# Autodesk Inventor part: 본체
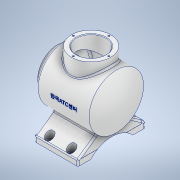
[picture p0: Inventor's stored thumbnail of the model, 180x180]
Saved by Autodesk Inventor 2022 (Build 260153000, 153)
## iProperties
Created: 2023-04
Part Number: 본체
Material: 알루미늄 6061
Document SubType Name: Modeling
Designer: Admin
Mass: 1268.09 g
Surface Area: 1064.58 cm^2
Volume: 469.663 cm^3
Density: 2.7 g/cm^3
Appearance: 알루미늄 - 평지
Author: Admin
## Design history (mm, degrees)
sketch "스케치1"
  geometry: L1 (-78.235, 0)-(97.232, 0) reference; L2 (0, -29.127)-(0, 63.971) reference; L3 (-48.168, 50)-(48.168, 50); L4 (48.168, 50)-(48.168, 0); L5 (-48.168, 0)-(-48.168, 50); L6 (-48.168, 0)-(72.165, 0); A1 r 113 centre (-53.168, 0) between (59.832, 0) and (48.168, 50); 3 further points
  constraints: 8 end point, 5 point on line, 3 point on circle, 1 centre point, 1 collinear, 1 horizontal, 1 parallel, 1 perpendicular, 1 other
  dimensions: "d2" = 100 diameter of L3 L1; "d3" = 23.99706 distance from line of L6.end L4; "d5" = 113 radius of A1; "d16" = 108 distance from line of A1.start L5
revolve "회전1" sketch "스케치1" stored, may be unused: angle "d4" = 360 deg
sketch "스케치2"
  geometry: L1 (0, -70)-(0, 70) reference; L2 (-70, 0)-(70, 0) reference; C1 r 36 at (0, 0); 1 further point
  constraints: 1 centre point, 1 coincident
  dimensions: "d7" = 72 diameter of C1
extrude "돌출1" join sketch "스케치2" distance "d8" = 12; taper "d9" = 0 deg
node "작업 평면1"
sketch "스케치3"
  geometry: L1 (81.835, 0)-(-69.835, 0) reference; L2 (0, -86.8)-(0, 86.8) reference; L3 (60.168, -36)-(60.168, 36) reference; L4 (48.168, 36)-(48.168, -36) reference; L5 (48.168, 50)-(48.168, -50) reference; L6 (-48.168, 50)-(-48.168, -50) reference; L7 (-48.168, 50)-(-48.168, -50) reference; L8 (40.168, -62)-(-39.832, -62); L9 (-39.832, -62)-(-39.832, 62); L10 (-39.832, 62)-(40.168, 62); L11 (40.168, 62)-(40.168, -62); L12 (40.168, -62)-(-39.832, 62); L13 (-39.832, -62)-(40.168, 62); 2 further points
  constraints: 12 end point, 2 midpoint, 2 parallel, 1 horizontal, 1 perpendicular, 1 point on line
  dimensions: "d11" = 80 distance of L8.start L8.end; "d12" = 124 distance of L8.end L9.end; "d13" = 20 distance between parallel lines of L3 L11
extrude "돌출2" join sketch "스케치3" distance "d14" = 10; taper "d15" = 0 deg
sketch "스케치4"
  geometry: L1 (-67, 62)-(-42.278, 26.694); L2 (-77, 62)-(-67, 62) reference; L3 (-77, -62)-(-67, -62) reference; L4 (-67, 62)-(-67, -62) reference; L5 (-67, -62)-(-42.278, -26.694); L6 (0, -86.8)-(0, 86.8) reference; L7 (-102.4, 0)-(75.4, 0) reference; L8 (-67, -62)-(-67, 62); C1 r 36 at (0, 0) reference; C2 r 36 at (0, 0) reference; C3 r 50 at (0, 0); A1 r 50 centre (0, 0) between (-42.278, 26.694) and (-42.278, -26.694) reference; A2 r 50 centre (0, 0) between (-42.278, 26.694) and (-42.278, -26.694) reference; 3 further points
  constraints: 6 end point, 2 point on circle, 1 centre point, 1 coincident, 1 perpendicular
  dimensions: "d17" = 55 deg angle of L2 L1; "d19" = 55 deg angle of L3 L5; "d20" = 100 diameter of C3
extrude "돌출3" join sketch "스케치4" stored distance "d21" = 80; taper "d22" = 0 deg
sketch "스케치5"
  geometry: L1 (62, -61.725)-(62, 158.454) reference; L2 (-24.8, 77)-(148.8, 77) reference; L3 (124, 0)-(0, 0) reference; L4 (0, 0)-(0, 10) reference; L5 (23.5, 0)-(100.5, 0); L6 (62, 17)-(73.395, 17); A1 r 52.096 centre (62, -35.096) between (100.5, 0) and (23.5, 0); 1 further point
  constraints: 4 end point, 3 point on circle, 2 point on line, 1 centre point, 1 collinear, 1 horizontal, 1 tangent, 1 other
  dimensions: "d23" = 77 distance of L5.start L5.end; "d24" = 23.5 distance from line of L5.start L4; "d117" = 17 distance from line of L3 L6.start
extrude "돌출4" cut sketch "스케치5" extent not by distance; stored distance "d26" = 80; taper "d27" = 0 deg
node "작업 평면2"
sketch "스케치6"
  geometry: L1 (79.768, 0)-(-57.432, 0) reference; L2 (0, -50.4)-(0, 50.4) reference; L3 (60.168, -36)-(60.168, 36) reference; C1 r 36 at (-1.832, 0); 1 further point
  constraints: 1 centre point, 1 point on line
  dimensions: "d32" = 72 diameter of C1; "d33" = 62 distance from line of L3 C1.centre
extrude "돌출5" join sketch "스케치6" stored distance "d34" = 10; taper "d35" = 0 deg
sketch "스케치7"
  geometry: L1 (-86, 0)-(82, 0) reference; L2 (-62, 36)-(-62, -36) reference; L3 (38, 62)-(-41.832, 62) reference; C1 r 27 at (0, 0); 1 further point
  constraints: 1 centre point
  dimensions: "d36" = 54 diameter of C1; "d37" = 62 distance from line of L2 C1.centre; "d38" = 62 distance from line of L3 C1.centre
sketch "스케치8"
  geometry: C1 r 27 at (0, 0); 1 further point
  constraints: 1 centre point, 1 coincident
  dimensions: "d39" = 54 diameter of C1
extrude "돌출6" cut sketch "스케치8" distance "d40" = 19; taper "d41" = 0 deg
sketch "스케치9"
  geometry: L1 (-41.168, -27)-(-41.168, 27) reference; L2 (-41.168, 0)-(45.331, 0); L3 (45.331, 0)-(45.331, 43); L4 (45.331, 43)-(-41.168, 43); L5 (-41.168, 43)-(-41.168, 0); L6 (-84.168, 0)-(83.832, 0) reference; L7 (0, -70)-(0, 70) reference; L8 (53.832, 0)-(45.331, 0); L9 (-60.168, -27)-(-60.168, 27) reference; L10 (53.832, 0)-(45.331, 0); L11 (53.832, 0)-(45.331, 0); L12 (48.168, -50)-(48.168, 50) reference; A1 r 113 centre (-59.168, 0) between (53.832, 0) and (45.331, 43); A2 r 113 centre (-53.168, 0) between (48.168, -50) and (48.168, 50) reference; 2 further points
  constraints: 14 end point, 3 point on circle, 3 point on line, 2 collinear, 2 parallel, 2 perpendicular, 1 centre point, 1 horizontal, 1 midpoint
  dimensions: "d42" = 86 diameter of L4 L6; "d44" = 113 radius of A1; "d45" = 114 distance from line of L9 L8.start
revolve "회전2" sketch "스케치9" stored, may be unused: angle "d46" = 90 deg
sketch "스케치10"
  geometry: 1 further point
extrude "돌출7" cut sketch "스케치7" stored distance "d47" = 19; taper "d48" = 0 deg
sketch "스케치11"
  geometry: L1 (-86, 0)-(82, 0) reference; L2 (38, 62)-(-41.832, 62) reference; L3 (-62, 36)-(-62, -36) reference; A1 r 32.5 centre (0, 0) between (32.5, 0) and (0, -32.5); 3 further points
  constraints: 4 point on circle, 2 point on line, 1 centre point
  dimensions: "d49" = 65 diameter of A1; "d50" = 62 distance from line of L2 A1.centre; "d51" = 62 distance from line of L3 A1.centre
hole "구멍1" sketch "스케치11" at (32.5, 0), (0, -32.5), (-32.5, 0), (0.249, 32.499) diameter "d52" = 3.242; stored, may be unused: countersink angle "d56" = 90 deg, drill point angle "d58" = 118 deg; dims "d53" = 8, "d54" = 4, "d55" = 2, "d57" = 10
sketch "스케치14"
  geometry: L1 (0, -70)-(0, 70) reference; L2 (-70, 0)-(70, 0) reference; A1 r 32.5 centre (0, 0) between (0, 32.5) and (32.5, 0); 3 further points
  constraints: 4 point on circle, 4 point on line, 1 centre point, 1 coincident
  dimensions: "d59" = 65 diameter of A1
hole "구멍2" sketch "스케치14" at (0, 32.5), (32.5, 0), (0, -32.5), (-32.5, 0) diameter "d60" = 3.242; stored, may be unused: countersink angle "d64" = 90 deg, drill point angle "d66" = 118 deg; dims "d61" = 8, "d62" = 4, "d63" = 2, "d65" = 10
sketch "스케치15"
  geometry: L1 (39.832, 62)-(39.832, 38.5) reference; L2 (-40.168, 62)-(39.832, 62) reference; L3 (39.832, -38.5)-(39.832, -62) reference; L4 (39.832, -62)-(-40.168, -62) reference; 5 further points
  dimensions: "d67" = 20 distance from line of L1 point (19.832, 54); "d68" = 8 distance from line of L2 point (19.832, 54); "d69" = 40 distance of point (19.832, 54) point (-20.168, 54); "d70" = 8 distance from line of L2 point (-20.168, 54); "d71" = 20 distance from line of L3 point (19.832, -54); "d72" = 8 distance from line of L4 point (19.832, -54); "d73" = 8 distance from line of L4 point (-20.168, -54); "d74" = 40 distance of point (19.832, -54) point (-20.168, -54)
sketch "스케치16"
  geometry: 1 further point
hole "구멍3" sketch "스케치15" diameter "d75" = 9; stored, may be unused: countersink angle "d79" = 90 deg, drill point angle "d81" = 0 deg; dims "d76" = 40 (= d74), "d77" = 4, "d78" = 2, "d80" = 6
sketch "스케치21"
  geometry: L1 (60, -8)-(-20, -8) reference; L2 (-20, -8)-(-20, 15.5) reference; 2 further points
  dimensions: "d97" = 8 distance from line of L1 point (0, 0); "d98" = 20 distance from line of L2 point (0, 0)
hole "구멍4" sketch "스케치21" at (0, 0) diameter "d99" = 14; stored, may be unused: countersink angle "d103" = 90 deg, drill point angle "d105" = 0 deg; dims "d100" = 6, "d101" = 4, "d102" = 2, "d104" = 14
node "작업 평면3"
sketch "스케치22"
  geometry: L1 (-60.168, 36)-(-60.168, -36) reference; L2 (37.832, 65)-(-34.168, 65) reference; L3 (-40.168, -77)-(39.832, -77) reference; 2 further points
  constraints: 1 other
  dimensions: "d106" = 62 distance from line of L1 point (1.832, 0); "d108" = 77 distance from line of L3 point (1.832, 0)
feature "엠보싱1" sketch "스케치22" dims "d2" = 100, "d3" = 23.99706, "d5" = 113, "d16" = 108, "d109" = 0.5, "d110" = 0
fillet "모깎기1" dims "d111" = 3
chamfer "모따기1" distance "d112" = 1; stored, may be unused: second distance "d113" = 2, angle "d114" = 45 deg
fillet "모깎기3" dims "d116" = 2
fillet "모깎기4" dims "d118" = 3
node "솔리드1"
mirror "미러2"
mirror "미러3"
node "투영된 루프1"
node "투영된 루프2"
node "투영된 루프3"
node "투영된 루프4"
feature "A9D066F2-1C7D-4E18-AEED-F7BC21143FA4" dims "d75" = 9, "d76" = 40 (= d74), "d77" = 4, "d78" = 2, "d79" = 90 deg, "d80" = 6, "d81" = 0
other parameters: "d10" = -77, "d31" = 65
